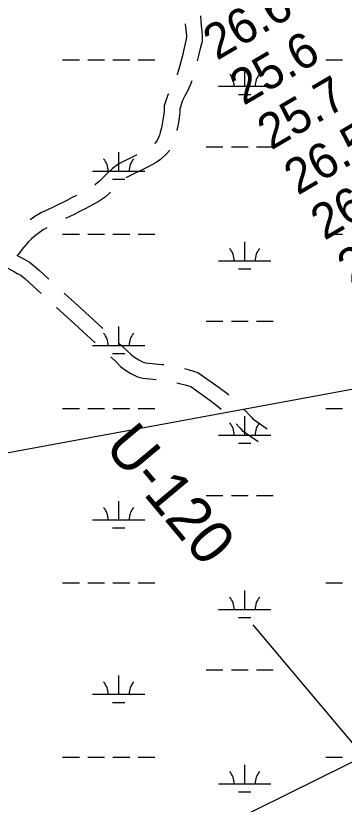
# Model space of a CAD drawing. Extents: x 3281947 to 3319794, y 715894 to 741249.
# Drawn here: x 3297059 to 3297686, y 735444 to 736948 of the extents above; entities that cross this region are included whole.
import ezdxf

# ---------------------------------------------------------------- set-up
doc = ezdxf.new("R2010")
doc.units = 0
for name, color, linetype in [('V-RIVR-EDGE', 7, 'Continuous'), ('V-RIVR-RANG', 7, 'Continuous'), ('V-RIVR-RANG-IDEN', 7, 'Continuous'), ('V-ROAD-CNTR', 7, 'Continuous'), ('V-TOPO-MAJR', 7, 'Continuous'), ('V-WETL-SWMP', 7, 'Continuous')]:
    doc.layers.add(name, color=color, linetype=linetype)

msp = doc.modelspace()

# ---------------------------------------------------------------- linework, layer by layer
at = {"layer": 'V-RIVR-EDGE'}
msp.add_spline([(3306927.3, 739468.3), (3306926.1, 739467.2), (3306903.7, 739453.6), (3306870.1, 739429.2), (3306847.2, 739417.3), (3306829.8, 739410.7), (3306783.3, 739383), (3306752.2, 739364.9), (3306726.1, 739348.8), (3306702.4, 739335.1), (3306685, 739324.8), (3306665.9, 739314.9), (3306638.9, 739297.2), (3306600.3, 739272.8), (3306545.5, 739237.3), (3306523, 739219.9), (3306470.3, 739190.2), (3306401.4, 739148.1), (3306343.7, 739117.2), (3306258.7, 739071.4), (3306203, 739040.4), (3306174.4, 739028.5), (3306163.2, 739023.5), (3306146.6, 739012.8), (3306119.2, 738998.8), (3306082.7, 738977.7), (3306000.9, 738937.3), (3305897.2, 738886.6), (3305874.4, 738874.6), (3305858.6, 738869.3), (3305835.4, 738857.3), (3305801.3, 738840), (3305781, 738829.7), (3305760.2, 738823.1), (3305753.2, 738819), (3305734.9, 738806.2), (3305715.8, 738794.2), (3305680.1, 738778.9), (3305650.3, 738771.1), (3305639.1, 738767.9), (3305612.5, 738755.1), (3305581, 738740.6), (3305562.7, 738732.4), (3305542, 738719.6), (3305524.1, 738713), (3305499.2, 738706.4), (3305484.7, 738701.1), (3305439.9, 738673.8), (3305385.9, 738638.8), (3305341.5, 738613.2), (3305295, 738585.1), (3305260.6, 738568.6), (3305238.6, 738557), (3305221.1, 738546.7), (3305195, 738536.8), (3305174.3, 738531.1), (3305162.7, 738528.2), (3305151, 738521.2), (3305133.2, 738510.9), (3305120.7, 738504.7), (3305108.3, 738501.4), (3305096.3, 738496.9), (3305067.6, 738482), (3305036.5, 738467.6), (3305010, 738456.9), (3304984.6, 738443.7), (3304966.8, 738435.9), (3304935.7, 738426.8), (3304922.4, 738419.8), (3304917, 738414), (3304911.2, 738410.3), (3304904.6, 738406.6), (3304892.5, 738401.6), (3304880.5, 738399.2), (3304872.6, 738396.7), (3304863.5, 738393), (3304850.2, 738385.2), (3304841.5, 738379.4), (3304833.2, 738377.7), (3304818.3, 738378.2), (3304809.6, 738374.9), (3304778.9, 738365.9), (3304753.1, 738358.1), (3304727.4, 738348.6), (3304707.9, 738338.3), (3304689.2, 738325.9), (3304632.4, 738306.1), (3304574.7, 738288.9), (3304543.6, 738278.6), (3304508.4, 738263.7), (3304471.9, 738248.1), (3304454.8, 738243.1), (3304430.8, 738241.6), (3304416.3, 738244.1), (3304384, 738249.5), (3304362.9, 738252.5), (3304345.9, 738250.9), (3304333.8, 738250.5), (3304318.5, 738245.6), (3304302.7, 738236.9), (3304285.7, 738220.8), (3304275.7, 738214.6), (3304263.7, 738208.8), (3304255.8, 738202.6), (3304240.8, 738187.7), (3304227.1, 738174.9), (3304205.5, 738159.2), (3304180.2, 738143.1), (3304166.9, 738134.4), (3304163.2, 738129.1), (3304156.1, 738118.3), (3304146.1, 738111.7), (3304128.7, 738103.4), (3304110.9, 738098.1), (3304071.5, 738083.3), (3303987.3, 738052.4), (3303903.4, 738017.4), (3303874.4, 738005), (3303826.7, 737986.9), (3303754.5, 737961.4), (3303700.6, 737937.9), (3303635.8, 737912.3), (3303612.2, 737899.6), (3303591.4, 737889.7), (3303550, 737877.7), (3303524.6, 737869.9), (3303506.8, 737863.8), (3303479, 737851.8), (3303451.6, 737837.8), (3303415.5, 737823.8), (3303344.6, 737794.1), (3303284.4, 737764.4), (3303262, 737752.9), (3303237.9, 737737.2), (3303213, 737724), (3303186, 737709.5), (3303142.5, 737690.2), (3303097.6, 737667.5), (3303032.5, 737639.4), (3302976.5, 737617.2), (3302929.2, 737601.2), (3302876.5, 737583), (3302830.5, 737568.7), (3302796, 737555.9), (3302747.5, 737537.8), (3302720.1, 737525.4), (3302695.2, 737512.2), (3302675.3, 737499.8), (3302664.1, 737496.9), (3302635.5, 737484.2), (3302576.1, 737459.9), (3302548.7, 737447.1), (3302510.2, 737433.1), (3302457.5, 737413.7), (3302421, 737398.1), (3302391.1, 737388.6), (3302329.3, 737363.9), (3302286.5, 737344.9), (3302210.2, 737311.1), (3302137.6, 737284.8), (3302109.4, 737273.3), (3302087, 737264.2), (3302049.2, 737245.6), (3302019.7, 737230.8), (3301976.6, 737211.4), (3301950.4, 737201.1), (3301943.4, 737198.2), (3301933.8, 737194.1), (3301894, 737176.4), (3301809.4, 737136.8), (3301743.4, 737108.4), (3301680.7, 737080.7), (3301627.6, 737053.9), (3301579.5, 737032.9), (3301552.9, 737023), (3301534.3, 737014.8), (3301493.6, 736995.8), (3301411, 736954.6), (3301362, 736929.4), (3301310.6, 736905.5), (3301262.9, 736882.4), (3301215.1, 736859.7), (3301178.2, 736842), (3301149.6, 736826.7), (3301101.4, 736800.3), (3301041.7, 736769.4), (3300976.1, 736738.5), (3300927.5, 736714.1), (3300864.5, 736682.4), (3300815.5, 736658), (3300740.4, 736620.9), (3300694.7, 736598.2), (3300652, 736576.8), (3300615, 736559.9), (3300570.6, 736537.6), (3300525.4, 736513.7), (3300478.5, 736490.2), (3300412.1, 736457.6), (3300368.5, 736435.3), (3300334.5, 736417.2), (3300322.5, 736411.8), (3300311.3, 736408.9), (3300299.2, 736406.1), (3300295.5, 736406.1), (3300294.7, 736404.4), (3300294.7, 736397), (3300281.4, 736392.4), (3300255.2, 736375.9), (3300190.5, 736346.2), (3300137.8, 736319.4), (3300120.8, 736312.4), (3300104.6, 736304.2), (3300099.2, 736299.2), (3300086.3, 736291.4), (3300046.9, 736269.9), (3299993, 736243.1), (3299941.9, 736215), (3299871.8, 736177.5), (3299788.3, 736128.8), (3299655.9, 736055.8), (3299580.8, 736015.3), (3299521, 735981.5), (3299470, 735950.5), (3299434.7, 735930.7), (3299399, 735909.7), (3299352.9, 735884.9), (3299310.2, 735863.1), (3299289, 735851.9), (3299266.2, 735838.3), (3299249.2, 735827.1), (3299241.3, 735819.3), (3299240, 735816.4), (3299238.4, 735813.1), (3299235.9, 735811), (3299230.5, 735809.4), (3299225.1, 735806.9), (3299193.9, 735785.8), (3299175.7, 735777.2), (3299154.9, 735764), (3299106.4, 735732.6), (3299056.5, 735703.7), (3299005.5, 735671.9), (3298964, 735645.9), (3298895.1, 735610.8), (3298849, 735583.2), (3298815, 735563.8), (3298791.3, 735550.2), (3298777.2, 735542.3), (3298768.5, 735541.5), (3298762.3, 735542.4), (3298759.8, 735543.2), (3298757.3, 735542), (3298755.2, 735538.2), (3298752.3, 735529.1), (3298741.9, 735517.9), (3298733.2, 735507.6), (3298717.8, 735496), (3298693.3, 735486.2), (3298651.8, 735458.9), (3298592, 735419.7), (3298532.2, 735380), (3298484.1, 735349.9), (3298445.1, 735323.9), (3298407.3, 735299.1), (3298382.8, 735283.4), (3298379.1, 735283.4), (3298372.4, 735288), (3298370.4, 735286.3), (3298373.3, 735281.4), (3298375.3, 735278.5), (3298372.4, 735275.1), (3298357.5, 735264.8), (3298336.3, 735249.1), (3298313.9, 735235.1), (3298289.4, 735216.5), (3298260.3, 735195.8), (3298236.6, 735177.2), (3298208.4, 735155.8), (3298183.1, 735137.2), (3298161.5, 735121.9), (3298140.3, 735103.3), (3298125.3, 735088.8), (3298116.2, 735078.9), (3298113.7, 735074.3), (3298097.1, 735060.7), (3298092.5, 735061.1), (3298082.6, 735052), (3298053.1, 735031), (3298015.7, 735004.1), (3297985.4, 734984.3), (3297950.9, 734959.5), (3297922.3, 734938.9), (3297903.6, 734926.5), (3297899, 734921.9), (3297888.6, 734910.4), (3297879.9, 734901.3), (3297866.2, 734893.4), (3297848.8, 734885.6), (3297830.5, 734869.5), (3297800.2, 734841.8), (3297778.2, 734825.2), (3297773.2, 734817.4), (3297767.8, 734817.4), (3297757.8, 734811.2), (3297737.1, 734797.2), (3297708.8, 734775.3), (3297691.8, 734762), (3297669, 734745.9), (3297649, 734731.9), (3297632.4, 734721.6), (3297622.9, 734718.3), (3297613.3, 734713.7), (3297603.8, 734704.2), (3297598.4, 734695.5), (3297582.6, 734681.1), (3297559.3, 734659.2), (3297519.9, 734623.6), (3297490, 734601.3), (3297462.6, 734580.6), (3297445.5, 734565.8), (3297435.2, 734559.2), (3297418.1, 734548.8), (3297407.3, 734538.5), (3297396.9, 734528.6), (3297386.1, 734512.9), (3297377.8, 734501.7), (3297353.3, 734483.5), (3297326.3, 734462), (3297292.3, 734431.4), (3297270.2, 734412.4), (3297255.3, 734402.9), (3297250.3, 734400.5), (3297246.6, 734394.3), (3297246.1, 734389.7), (3297243.7, 734387.6), (3297231.6, 734377.7), (3297218.3, 734367), (3297207.5, 734355.4), (3297200.9, 734347.1), (3297196.7, 734340.1), (3297165.1, 734312), (3297099.1, 734245.4), (3297065.4, 734212.7), (3297040.1, 734188.3), (3297027.6, 734178.4), (3297002.3, 734152.8), (3296989.4, 734134.6), (3296962.8, 734110.2)], degree=3, dxfattribs=at)
at = {"layer": 'V-RIVR-RANG'}
msp.add_line((3297511.6, 735786.3), (3298386.2, 734744.9), dxfattribs=at)
at = {"layer": 'V-ROAD-CNTR'}
for points in [[(3297411.2, 736948), (3297412.1, 736937.9), (3297412.5, 736929.6), (3297414, 736919.1), (3297414.5, 736910.4), (3297414.4, 736899.2), (3297411.2, 736888.3), (3297408.2, 736875.1), (3297406, 736864.9), (3297405.4, 736862.6)], [(3297382.3, 736933.1), (3297382.6, 736926.7), (3297384.1, 736916.1), (3297384.5, 736909.7), (3297384.4, 736903.6), (3297382.2, 736895.8), (3297378.9, 736881.6), (3297376.9, 736872), (3297374.4, 736863), (3297371.3, 736851.2), (3297368.8, 736842.5), (3297367.1, 736836.1), (3297366.8, 736835.5)], [(3297394.6, 736824.1), (3297391.6, 736815.7), (3297386.4, 736804.3), (3297381.4, 736795.5), (3297377.3, 736786.8), (3297372.1, 736770.9), (3297371.7, 736763.6), (3297370.6, 736753.4), (3297369.4, 736744.6), (3297366.4, 736729.3)], [(3297350.1, 736799.3), (3297349.4, 736797.8), (3297342.4, 736776.6), (3297341.8, 736766), (3297340.8, 736757), (3297339.8, 736749.6), (3297336.8, 736734.8), (3297334.6, 736725.5), (3297333.5, 736720.9), (3297330.9, 736714.4), (3297328.4, 736709.8), (3297324.9, 736705.6), (3297323.6, 736704.4)], [(3297352.7, 736692), (3297346.5, 736684.7), (3297335.4, 736674.5), (3297326.8, 736668.3), (3297310.5, 736659.7), (3297271.5, 736640.6), (3297269.2, 736638.9)], [(3297290.1, 736683.1), (3297255.5, 736666.2), (3297243.5, 736656.9), (3297235.4, 736649.1), (3297227.2, 736641.2), (3297218.5, 736632.7), (3297210.9, 736626.2), (3297209.6, 736625.3)], [(3297174.9, 736605.6), (3297166.8, 736601.6), (3297156.4, 736595.8), (3297114.7, 736575.7), (3297109.6, 736573.5), (3297095.4, 736565.7), (3297086.5, 736559.3)], [(3297239.9, 736611.7), (3297238.7, 736610.5), (3297229.3, 736602.4), (3297216.4, 736593.4), (3297205.6, 736587.5), (3297192.7, 736580.9), (3297180.7, 736575), (3297170.2, 736569.2), (3297154, 736561.4)], [(3297118, 736543.9), (3297111.5, 736540.3), (3297104, 736534.9), (3297096.6, 736529.4), (3297089.2, 736522.7), (3297082.6, 736516.2), (3297070.8, 736502.6), (3297068.5, 736499.5), (3297063.2, 736492.7), (3297060.9, 736490.5)], [(3297061.3, 736491.1), (3297070.5, 736486.3), (3297076, 736483.4), (3297085.2, 736478.2), (3297090.9, 736473.8), (3297096.1, 736469.6), (3297104.2, 736462.1), (3297121.8, 736446)], [(3297027.6, 736475), (3297056.6, 736459.7), (3297061.8, 736457), (3297068.6, 736453.2), (3297072.3, 736450.3), (3297076.4, 736446.9), (3297084, 736440), (3297107.3, 736418.7)], [(3297151.4, 736419.1), (3297191.2, 736382.7), (3297225.2, 736351.6)], [(3297136.8, 736391.7), (3297171, 736360.5), (3297210.7, 736324.3)], [(3297254.8, 736324.7), (3297271.1, 736309.8), (3297279, 736302), (3297283.7, 736298.3), (3297293.7, 736292.1), (3297302.2, 736287.6), (3297306.4, 736286.5), (3297337.8, 736283.3), (3297341.3, 736283)], [(3297240.2, 736297.4), (3297250.4, 736288), (3297259.1, 736279.5), (3297266.5, 736273.7), (3297278.7, 736266.1), (3297291.2, 736259.4), (3297301.1, 736256.9), (3297326.8, 736254.3)], [(3297380.6, 736275.4), (3297389.9, 736273.2), (3297406.6, 736268.1), (3297446.8, 736239.1), (3297461.5, 736228.3), (3297465.3, 736224.9)], [(3297366.2, 736248), (3297371.4, 736246.8), (3297382.1, 736244.3), (3297393.1, 736240.9), (3297429.1, 736214.9), (3297442.7, 736204.8), (3297450.9, 736197.7)], [(3297494.4, 736197.5), (3297494.5, 736197.4), (3297509.2, 736182.2), (3297511.6, 736179.2), (3297538.4, 736160.6)], [(3297479.5, 736169.8), (3297486.6, 736162.4), (3297490.9, 736157), (3297521.3, 736136)]]:
    msp.add_lwpolyline(points, dxfattribs=at)
at = {"layer": 'V-TOPO-MAJR'}
msp.add_lwpolyline([(3296886.3, 736086.1), (3297900.2, 736272.8), (3297911.7, 736279.5), (3297923.4, 736286.1), (3299564.5, 736587.7)], dxfattribs=at)
at = {"layer": 'V-WETL-SWMP'}
for p, q in [((3297148.4, 736864.6), (3297180.4, 736864.6)), ((3297196.4, 736864.6), (3297228.4, 736864.6)), ((3297244.4, 736864.6), (3297276.4, 736864.6)), ((3297292.4, 736864.6), (3297324.4, 736864.6)), ((3297650.3, 736864.6), (3297682.3, 736864.6)), ((3297495.8, 736813.8), (3297495.8, 736849.8)), ((3297445.8, 736813.8), (3297545.8, 736813.8)), ((3297483.8, 736798.4), (3297507.8, 736798.4)), ((3297255.3, 736652), (3297255.3, 736688)), ((3297422.3, 736698.4), (3297454.3, 736698.4)), ((3297470.3, 736698.4), (3297502.3, 736698.4)), ((3297518.3, 736698.4), (3297550.3, 736698.4)), ((3297205.3, 736652), (3297305.3, 736652)), ((3297243.3, 736636.5), (3297267.3, 736636.5)), ((3297148.4, 736531.9), (3297180.4, 736531.9)), ((3297196.4, 736531.9), (3297228.4, 736531.9)), ((3297244.4, 736531.9), (3297276.4, 736531.9)), ((3297292.4, 736531.9), (3297324.4, 736531.9)), ((3297650.3, 736531.9), (3297682.3, 736531.9)), ((3297495.8, 736481.1), (3297495.8, 736517.1)), ((3297445.8, 736481.1), (3297545.8, 736481.1)), ((3297483.8, 736465.7), (3297507.8, 736465.7)), ((3297422.3, 736365.7), (3297454.3, 736365.7)), ((3297470.3, 736365.7), (3297502.3, 736365.7)), ((3297518.3, 736365.7), (3297550.3, 736365.7)), ((3297255.3, 736319.3), (3297255.3, 736355.3)), ((3297205.3, 736319.3), (3297305.3, 736319.3)), ((3297243.3, 736303.8), (3297267.3, 736303.8)), ((3297148.4, 736199.2), (3297180.4, 736199.2)), ((3297196.4, 736199.2), (3297228.4, 736199.2)), ((3297244.4, 736199.2), (3297276.4, 736199.2)), ((3297292.4, 736199.2), (3297324.4, 736199.2)), ((3297650.3, 736199.2), (3297682.3, 736199.2)), ((3297495.8, 736148.5), (3297495.8, 736184.5)), ((3297445.8, 736148.5), (3297545.8, 736148.5)), ((3297483.8, 736133), (3297507.8, 736133)), ((3297422.3, 736033), (3297454.3, 736033)), ((3297470.3, 736033), (3297502.3, 736033)), ((3297518.3, 736033), (3297550.3, 736033)), ((3297255.3, 735986.6), (3297255.3, 736022.6)), ((3297205.3, 735986.6), (3297305.3, 735986.6)), ((3297243.3, 735971.2), (3297267.3, 735971.2)), ((3297148.4, 735866.5), (3297180.4, 735866.5)), ((3297196.4, 735866.5), (3297228.4, 735866.5)), ((3297244.4, 735866.5), (3297276.4, 735866.5)), ((3297292.4, 735866.5), (3297324.4, 735866.5)), ((3297650.3, 735866.5), (3297682.3, 735866.5)), ((3297495.8, 735815.8), (3297495.8, 735851.8)), ((3297445.8, 735815.8), (3297545.8, 735815.8)), ((3297483.8, 735800.4), (3297507.8, 735800.4)), ((3297422.3, 735700.4), (3297454.3, 735700.4)), ((3297470.3, 735700.4), (3297502.3, 735700.4)), ((3297518.3, 735700.4), (3297550.3, 735700.4)), ((3297255.3, 735653.9), (3297255.3, 735689.9)), ((3297205.3, 735653.9), (3297305.3, 735653.9)), ((3297243.3, 735638.5), (3297267.3, 735638.5)), ((3297148.4, 735533.9), (3297180.4, 735533.9)), ((3297196.4, 735533.9), (3297228.4, 735533.9)), ((3297244.4, 735533.9), (3297276.4, 735533.9)), ((3297292.4, 735533.9), (3297324.4, 735533.9)), ((3297650.3, 735533.9), (3297682.3, 735533.9)), ((3297495.8, 735483.1), (3297495.8, 735519.1)), ((3297445.8, 735483.1), (3297545.8, 735483.1)), ((3297483.8, 735467.7), (3297507.8, 735467.7))]:
    msp.add_line(p, q, dxfattribs=at)
msp.add_lwpolyline([(3297100, 735227.5), (3297991.9, 735668.7), (3298723.4, 736100), (3299535, 736491.1), (3300106.8, 736687.6), (3300106.8, 737201), (3300098.9, 737195.9), (3300078.2, 737189.3), (3300057.6, 737179.4), (3300026.7, 737173), (3299999.1, 737163.1), (3299981.9, 737153.1), (3299957.8, 737146.6), (3299933.7, 737133.3), (3299909.7, 737130.2), (3299892.6, 737130.5), (3299865.2, 737134.3), (3299855.1, 737141.3), (3299851.7, 737144.8), (3299851.8, 737148.2), (3299841.7, 737162.1), (3299845.3, 737175.7), (3299852.4, 737189.3)], dxfattribs=at)
for centre, start, end in [((3297440.5, 736814.3), 359.2282, 40.7718), ((3297551, 736814.3), 139.2282, 180.7718), ((3297200, 736652.4), 359.2282, 40.7718), ((3297310.5, 736652.4), 139.2282, 180.7718), ((3297440.5, 736481.6), 359.2282, 40.7718), ((3297551, 736481.6), 139.2282, 180.7718), ((3297200, 736319.8), 359.2282, 40.7718), ((3297310.5, 736319.8), 139.2282, 180.7718), ((3297440.5, 736148.9), 359.2282, 40.7718), ((3297551, 736148.9), 139.2282, 180.7718), ((3297200, 735987.1), 359.2282, 40.7718), ((3297310.5, 735987.1), 139.2282, 180.7718), ((3297440.5, 735816.3), 359.2282, 40.7718), ((3297551, 735816.3), 139.2282, 180.7718), ((3297200, 735654.4), 359.2282, 40.7718), ((3297310.5, 735654.4), 139.2282, 180.7718), ((3297440.5, 735483.6), 359.2282, 40.7718), ((3297551, 735483.6), 139.2282, 180.7718)]:
    msp.add_arc(centre, 35.2, start, end, dxfattribs=at)

# ---------------------------------------------------------------- texts
at = {"layer": 'V-RIVR-RANG'}
for s, p in [('26.6', (3297442.8, 736862.2)), ('25.6', (3297493.6, 736776.2)), ('25.7', (3297546.1, 736691)), ('26.5', (3297597, 736604.9)), ('26.2', (3297647.9, 736518.8)), ('26.5', (3297698.7, 736432.7))]:
    msp.add_text(s, height=67, rotation=30.4383, dxfattribs=at).set_placement(p)
at = {"layer": 'V-RIVR-RANG-IDEN'}
msp.add_text('U-120', height=83, rotation=309.8843, dxfattribs=at).set_placement((3297225.8, 736125.8))

doc.saveas('drawing.dxf')
